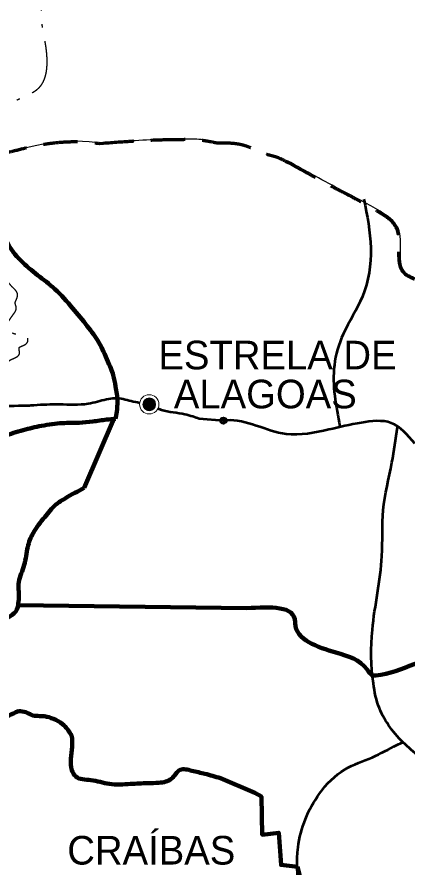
# Model space of a CAD drawing. Extents: x 512883 to 1063249, y 8784064 to 9081064.
# Drawn here: x 739180 to 759622, y 8936802 to 8981350 of the extents above; entities that cross this region are included whole.
import ezdxf

# ---------------------------------------------------------------- set-up
doc = ezdxf.new("R2010")
doc.units = 0
doc.header["$LTSCALE"] = 600
doc.header["$PDMODE"] = 32
doc.header["$PDSIZE"] = 300
doc.linetypes.add('DOT_DASHED', pattern=[7.7, 5, -1.2, 0.3, -1.2])
doc.linetypes.add('MEDIUM_DASHED', pattern=[4.5, 3, -1.5])
for name, color, linetype, lineweight in [('10', 7, 'Continuous', 53), ('13', 7, 'Continuous', 90), ('4', 7, 'Continuous', 13), ('5', 7, 'Continuous', 13)]:
    doc.layers.add(name, color=color, linetype=linetype, lineweight=lineweight)

msp = doc.modelspace()

# ---------------------------------------------------------------- linework, layer by layer
at = {"layer": '10'}
msp.add_line((748733, 8960303.9), (750009.2, 8960196.7), dxfattribs=at)
for points in [[(757362.8, 8971798.3), (757718.1, 8969235), (757286.6, 8966697.4), (756271.3, 8964723.6), (755814.4, 8963108.8), (756109.2, 8959887.7)], [(739750.2, 8960990), (740069.8, 8961013.6), (741413.6, 8961055), (742910, 8961091.3), (743877.1, 8961319.2), (744319.9, 8961381.4), (745159.8, 8961231.2), (745615.5, 8961134.3)], [(728165.2, 8959972.1), (728754.8, 8959967.2), (729599.7, 8960008.6), (730928.2, 8960262.5), (732088.7, 8960443.8), (734109.4, 8960775.3), (735885.8, 8960894.5), (739750.2, 8960990)], [(746576.9, 8960831.1), (746747.9, 8960770.1), (747984.7, 8960537), (748391.9, 8960423.1), (748733, 8960303.9)], [(760025.4, 8958989.5), (758791.9, 8960070.6), (757224, 8960086.4), (755519.6, 8959726.1), (753291.3, 8959489.3), (750147.9, 8960209.6), (749997.5, 8960195.6)], [(760373.1, 8942504.5), (759520.9, 8943232.2), (758173.4, 8945126.8), (757857.6, 8946419.7), (757806.3, 8949236.7), (758306.2, 8953099), (758380.2, 8955499.1), (758834.8, 8958004.7), (759126.7, 8959859.4)], [(753024.3, 8928810.8), (754028, 8932114.6), (753933.5, 8935630), (753912.2, 8937835.1), (755033.7, 8940646.8), (756371.5, 8941919.9), (757796.1, 8942548.3), (759099.7, 8943197.1), (759414.7, 8943351.8)]]:
    msp.add_spline(points, degree=3, dxfattribs=at)
msp.add_point((749997.5, 8960195.6), dxfattribs=at)
at = {"layer": '13'}
for p, q in [((742703.1, 8956675), (744263.7, 8960282.7)), ((739246.1, 8950519.4), (751215.9, 8950362.8))]:
    msp.add_line(p, q, dxfattribs=at)
msp.add_lwpolyline([(749838.3, 8941454.7), (751650.3, 8940681.7), (751994, 8940495), (752036.3, 8938491.8), (752899.3, 8938598.9), (753018.5, 8936908.9), (753888.2, 8936808.1)], dxfattribs=at)
at = {"layer": '13', "linetype": 'MEDIUM_DASHED', "lineweight": 70}
for points in [[(732593, 8973647.4), (733055.8, 8973679.3), (734017.8, 8973979.7), (735473.6, 8973984.9), (738247.6, 8974166.2), (740120.7, 8974596.2), (742869.3, 8974793), (743500, 8974726.3)], [(743500, 8974726.3), (746671.5, 8974917.3), (747832, 8974938.1), (748738.1, 8974912.2), (749654.2, 8974756.8)], [(749654.2, 8974756.8), (751133.8, 8974617.1), (752173.2, 8974188.4), (752784.7, 8974014.9), (753246, 8973806.2)], [(753258.6, 8973800.6), (756145, 8972228.3), (758126.6, 8971149.5), (759060.8, 8970276.1), (759489.1, 8967898.4), (760156.5, 8967525), (761008.9, 8966776.5), (761311.1, 8966714.8), (761418.5, 8967904.7), (761819.8, 8967968.6), (761964.4, 8967614.3), (763228, 8966032.4), (763365, 8966366.7), (763825, 8966576.9), (764463.7, 8966975.4), (765249.4, 8966811), (765751.8, 8966812.7), (766047.5, 8967335.3), (766506.4, 8968208.9)]]:
    msp.add_spline(points, degree=3, dxfattribs=at)
at = {"layer": '13', "lineweight": 25}
for points in [[(743591.5, 8974743), (742960.8, 8974809.7), (740212.2, 8974612.9), (738339.1, 8974182.9), (735565.1, 8974001.6), (734109.3, 8973996.4), (733147.3, 8973696), (732684.5, 8973664.1)], [(749745.8, 8974773.5), (748829.6, 8974928.9), (747923.6, 8974954.8), (746763.1, 8974934), (743591.5, 8974743)], [(766598, 8968225.6), (766139.1, 8967352), (765843.4, 8966829.4), (765340.9, 8966827.7), (764555.2, 8966992.2), (763916.5, 8966593.6), (763456.6, 8966383.4), (763319.6, 8966049.1), (762055.9, 8967631), (761911.3, 8967985.3), (761510.1, 8967921.4), (761402.6, 8966731.5), (761100.5, 8966793.2), (760248, 8967541.7), (759580.7, 8967915.2), (759152.4, 8970292.8), (758218.2, 8971166.2), (756236.6, 8972245), (753350.1, 8973817.3)]]:
    msp.add_spline(points, degree=3, dxfattribs=at)
at = {"layer": '13'}
for points in [[(736550.5, 8974034.8), (736820.9, 8972666.4), (737287.4, 8971829), (738159.6, 8970807.9), (738666.7, 8969562.1), (739376.6, 8968581.7), (741161.5, 8967090.8), (742094.6, 8966090.1), (742865.3, 8965150.7), (743473.8, 8964292.9), (743940.3, 8963292.1), (744224.3, 8962577.3), (744346, 8961985.1), (744447.4, 8961209), (744406.9, 8960657.6), (744346, 8960289.9)], [(726317.6, 8962899.8), (726638.7, 8962271), (727267.5, 8961372.4), (728180.3, 8960657.6), (729397.3, 8959799.8), (730411.4, 8959268.8), (731405.3, 8959064.6), (732581.7, 8958737.8), (733717.6, 8958676.5), (735076.6, 8958839.9), (736192.2, 8958962.4), (737206.3, 8959064.6), (738504.4, 8959391.3), (739498.3, 8959697.7), (740471.9, 8959922.3), (741567.2, 8960065.3), (742439.4, 8960085.7), (743149.3, 8960147), (743879.5, 8960249.1), (744346, 8960289.9)], [(718651.7, 8962582.6), (717835.8, 8961821.7), (716983.9, 8960187.8), (717450.4, 8959575.1), (717693.8, 8958982.8), (717633, 8958370.2), (717470.7, 8957634.9), (717146.2, 8956593.3), (717612.7, 8955470.1), (718058.9, 8954612.3), (718464.6, 8953570.7), (719519.3, 8952141.1), (720432.1, 8951222.1), (721507.1, 8950527.7), (722379.3, 8949853.7), (723271.7, 8949486.1), (724265.6, 8949098), (725198.6, 8948791.7), (726517, 8948730.4), (727652.9, 8948505.8), (728748.2, 8948505.8), (729519, 8948505.8), (730452, 8948505.8), (731831.2, 8948464.9), (732926.6, 8948464.9), (735076.6, 8948771.3), (736111, 8949077.6), (737003.5, 8949302.3), (737997.4, 8949445.2), (738687, 8949853.7), (739112.9, 8950200.9), (739275.2, 8950588.9)], [(739237.1, 8950497.7), (739275.2, 8950936.1), (739275.2, 8951732.6), (739559.2, 8952631.2), (739741.7, 8953570.7), (740025.7, 8954306), (740634.2, 8955143.3), (741222.4, 8955796.8), (741709.2, 8956123.6), (742703.1, 8956675)], [(751215.9, 8950362.8), (753762, 8949641), (753762.7, 8949578.4), (755890.1, 8948041), (757527.9, 8947149), (757853, 8946837), (757993.7, 8946837.5), (759997, 8947428.2), (761876.7, 8948289.9), (763609.1, 8949756.3), (764914.3, 8949864.8), (765859.8, 8949784.4), (767129, 8949517.2), (767844.7, 8948413.5), (770470.8, 8945520.4)], [(737832.4, 8943347.8), (737832.4, 8943843.3), (737997.6, 8944173.7), (738252.8, 8944429), (739258.5, 8944969.6)], [(742035.3, 8943697.1), (741570.4, 8944293.8), (741090, 8944564.2), (740624.6, 8944699.3), (739934.1, 8944774.4), (739648.8, 8944909.5), (739258.5, 8944969.6)], [(742021.1, 8943746), (742035.7, 8943693.2), (742005.7, 8942476.8), (742050.7, 8941876.2), (742256.8, 8941541.5), (743047.9, 8941357.7), (744021.5, 8941153.4), (745137.1, 8941153.4), (746029.5, 8941194.3), (746617.7, 8941214.7), (747287.1, 8941439.3), (747733.3, 8941888.7), (748341.8, 8941847.8), (749031.4, 8941684.4), (749838.3, 8941454.7)], [(749661.4, 8931331.2), (753736.3, 8933801.9), (753933.3, 8934157.3), (754010.5, 8936265.2), (753883.7, 8936828.2)]]:
    msp.add_spline(points, degree=3, dxfattribs=at)
at = {"layer": '4', "linetype": 'DOT_DASHED', "lineweight": 25}
for points in [[(737771.9, 8973878.1), (738007.4, 8976016.7), (739042.5, 8976929.5), (740383.3, 8977697.2), (740702.9, 8979750.7), (740453.3, 8981596.7), (740956.7, 8983442.9), (741968, 8985558.7), (742250.1, 8986512.9), (742185.8, 8987633), (742689.7, 8989292.4), (743519, 8990993.4)], [(737946.5, 8962644.2), (738502.1, 8962723.1), (738588.6, 8963033.9), (738731.1, 8963303.3), (739097.6, 8963500.1), (739316.5, 8963722.9), (739291, 8964002.6), (739591.3, 8964173.5), (739749.1, 8964370.4), (739642.2, 8964665.7), (739464.1, 8964727.8), (739087.4, 8964727.8), (738878.8, 8964815.9), (738649.7, 8965142.2), (738782, 8965468.6), (738960.2, 8965727.6), (739143.4, 8966121.3), (739087.4, 8966370), (739153.6, 8966556.4), (739209.6, 8966820.6), (738899.1, 8967235.1), (738593.7, 8967675.4), (738344.3, 8968162.3), (738217.1, 8968359.2), (737967.6, 8968483.5), (737484.1, 8968680.3), (737285.6, 8968866.8), (737112.5, 8969188), (737087.1, 8969576.5), (737087.1, 8969814.8), (737336.5, 8970089.4), (737499.4, 8970462.3), (737499.4, 8970907.8), (737641.9, 8971239.4), (737484.1, 8971591.6), (737509.5, 8971778.1), (737667.3, 8972249.5), (737667.3, 8972570.7), (737611.3, 8972891.9), (737626.6, 8972995.5), (737687.7, 8973446.2), (737779.3, 8973746.6), (737753.9, 8973974.5), (737708.1, 8974155.8), (737692.8, 8974186.9)]]:
    msp.add_spline(points, degree=3, dxfattribs=at)
at = {"layer": '5'}
for p, q in [((745779.1, 8961059.1), (746443.9, 8961059.1)), ((745779.7, 8961029.1), (746443.6, 8961029.1)), ((745781.2, 8961089.1), (746441.8, 8961089.1)), ((745782.7, 8960999.1), (746440.3, 8960999.1)), ((745786, 8961119.1), (746437, 8961119.1)), ((745788.7, 8960969.1), (746434.3, 8960969.1)), ((745794.1, 8961149.1), (746428.9, 8961149.1)), ((745797.7, 8960939.1), (746425.3, 8960939.1)), ((745804.9, 8961179.1), (746418.1, 8961179.4)), ((745819.3, 8961209.1), (746404, 8961209.1)), ((745837.6, 8961239.1), (746385.7, 8961239.1)), ((745861.6, 8961269.1), (746362, 8961269.1)), ((745890.7, 8961299.1), (746332.3, 8961299.1)), ((745930.3, 8961329.1), (746292.7, 8961329.1)), ((745987.6, 8961359.1), (746235.4, 8961359.1)), ((745810.3, 8960909.1), (746413, 8960909.4)), ((745826.2, 8960879.1), (746396.8, 8960879.1)), ((745846.9, 8960849.1), (746376.4, 8960849.4)), ((745872.1, 8960818.8), (746351.2, 8960819.1)), ((745905.4, 8960789.1), (746317.6, 8960789.1)), ((745950.4, 8960759.1), (746272.6, 8960759.1)), ((746024.2, 8960729.1), (746198.5, 8960729.1))]:
    msp.add_line(p, q, dxfattribs=at)
for radius in [506.1, 332.9]:
    msp.add_circle((746111.5, 8961050.1), radius, dxfattribs=at)

# ---------------------------------------------------------------- texts
for s, p in [('ESTRELA DE', (746590.3, 8962884.2)), ('ALAGOAS', (747400.9, 8960840.2)), ('CRAÍBAS', (741816, 8936929.9))]:
    msp.add_text(s, height=1500, dxfattribs=at).set_placement(p)

doc.saveas('drawing.dxf')
